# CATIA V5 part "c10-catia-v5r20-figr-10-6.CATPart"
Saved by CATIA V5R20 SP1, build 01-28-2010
Part number: Part1
Bounding box of the stored display mesh (mm): x -9.616 to 10, y -9.533 to 9.835, z 0 to 10
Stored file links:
  D:\v5_r20\psrt_files_downloaded\c10\c10-catia-v5r20-figr-10-6.CATPart
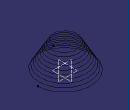
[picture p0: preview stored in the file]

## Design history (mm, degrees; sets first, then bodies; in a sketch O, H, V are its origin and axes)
Set1
  Helix1: Direction {line stored without definition}, RefPoint {point type Coord, X 10, Y 0, Z 0}, Pitch 1, Height 10, TaperAngle 30
Body1 (main body)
